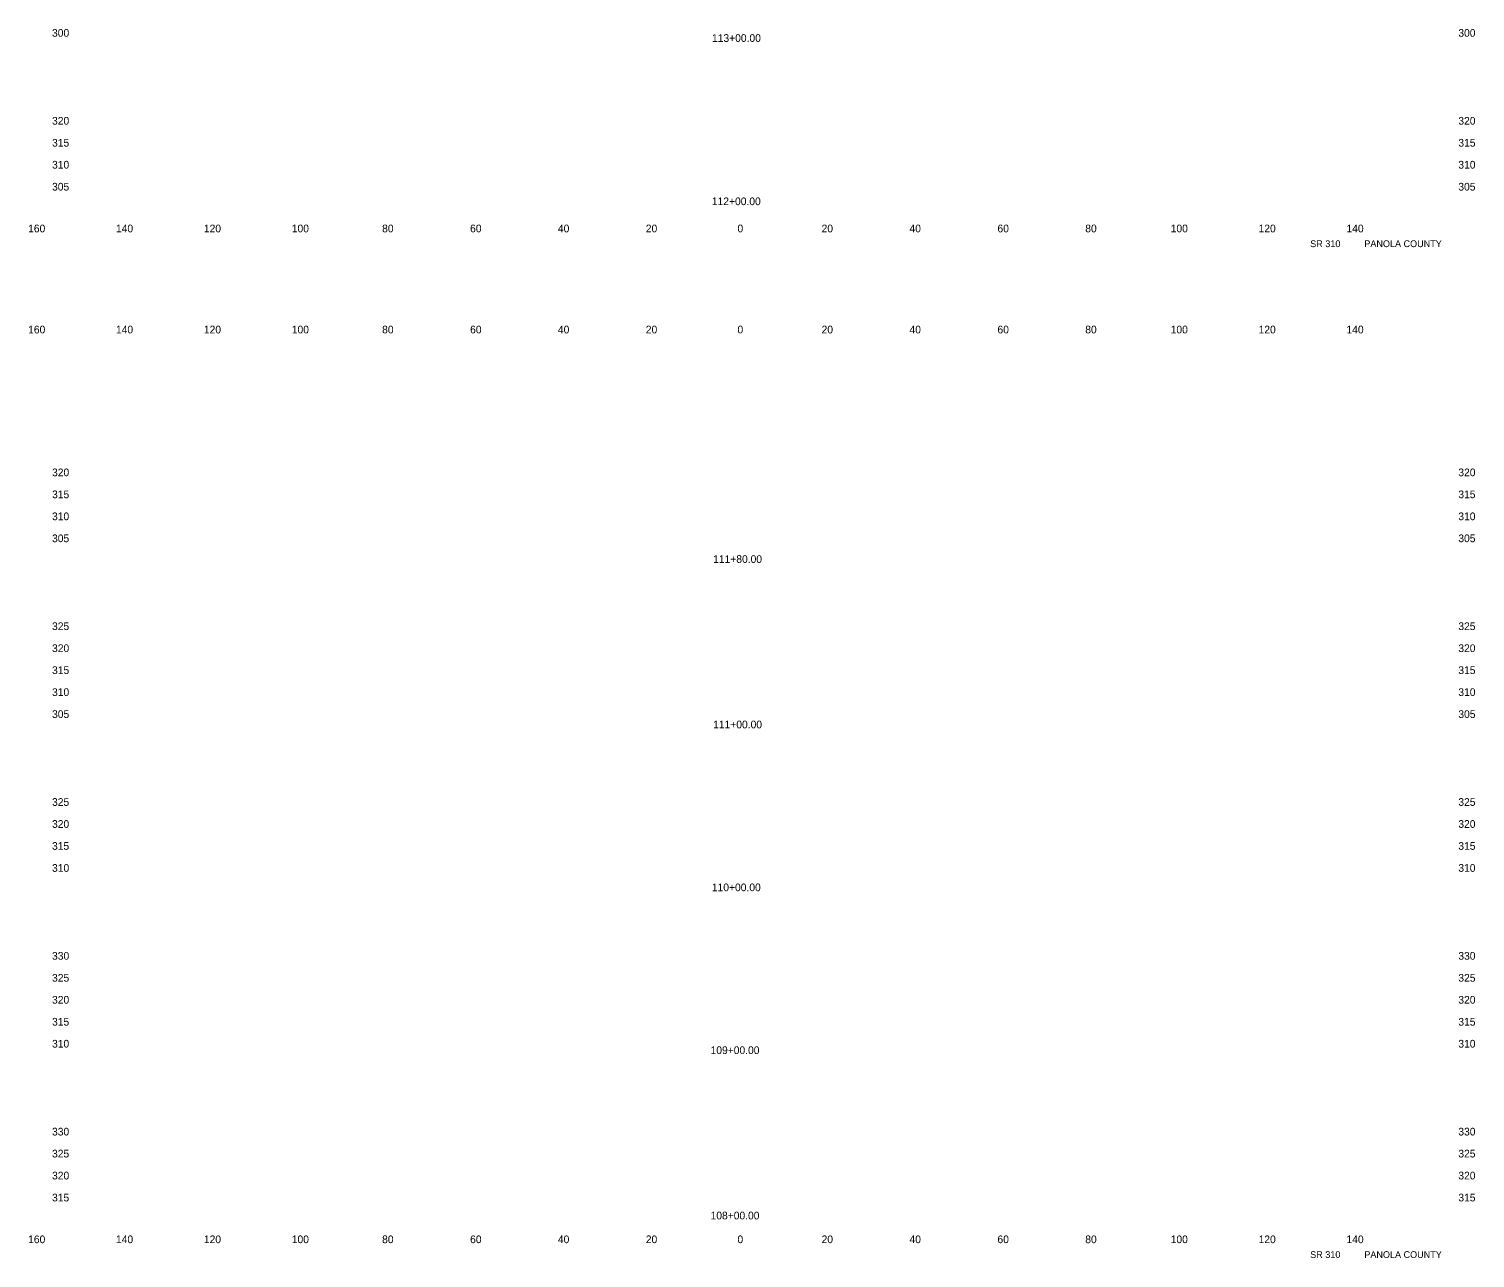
# Model space of a CAD drawing. Extents: x 21481 to 21810, y 6485 to 11067.
# Drawn here: x 21480.9 to 21809.9, y 7634.8 to 7914.5 of the extents above; entities that cross this region are included whole.
import ezdxf

# ---------------------------------------------------------------- set-up
doc = ezdxf.new("R2010")
doc.units = 0
for name, color, linetype in [('62', 7, 'Continuous'), ('XS_CELL', 7, 'Continuous'), ('XS_P_TX_DCH', 7, 'Continuous'), ('XS_P_TX_FS_BS', 7, 'Continuous')]:
    doc.layers.add(name, color=color, linetype=linetype)

msp = doc.modelspace()

# ---------------------------------------------------------------- texts
at = {"layer": '62'}
for s, p in [('  160  ', (21479.4, 7868.21)), ('  140  ', (21499.39, 7868.21)), ('  120  ', (21519.39, 7868.21)), ('  100  ', (21539.39, 7868.21)), ('  80  ', (21559.95, 7868.21)), ('  60  ', (21579.97, 7868.21)), ('  40  ', (21599.95, 7868.21)), ('  20  ', (21619.95, 7868.21)), ('  0  ', (21640.81, 7868.21)), ('  0  ', (21640.81, 7868.21)), ('  20  ', (21659.95, 7868.21)), ('  40  ', (21679.95, 7868.21)), ('  60  ', (21699.97, 7868.21)), ('  80  ', (21719.95, 7868.21)), ('  100  ', (21739.39, 7868.21)), ('  120  ', (21759.39, 7868.21)), ('  140  ', (21779.39, 7868.21)), ('  160  ', (21479.4, 7845.21)), ('  140  ', (21499.39, 7845.21)), ('  120  ', (21519.39, 7845.21)), ('  100  ', (21539.39, 7845.21)), ('  80  ', (21559.95, 7845.21)), ('  60  ', (21579.97, 7845.21)), ('  40  ', (21599.95, 7845.21)), ('  20  ', (21619.95, 7845.21)), ('  0  ', (21640.81, 7845.21)), ('  0  ', (21640.81, 7845.21)), ('  20  ', (21659.95, 7845.21)), ('  40  ', (21679.95, 7845.21)), ('  60  ', (21699.97, 7845.21)), ('  80  ', (21719.95, 7845.21)), ('  100  ', (21739.39, 7845.21)), ('  120  ', (21759.39, 7845.21)), ('  140  ', (21779.39, 7845.21)), ('  160  ', (21479.4, 7638.21)), ('  140  ', (21499.39, 7638.21)), ('  120  ', (21519.39, 7638.21)), ('  100  ', (21539.39, 7638.21)), ('  80  ', (21559.95, 7638.21)), ('  60  ', (21579.97, 7638.21)), ('  40  ', (21599.95, 7638.21)), ('  20  ', (21619.95, 7638.21)), ('  0  ', (21640.81, 7638.21)), ('  0  ', (21640.81, 7638.21)), ('  20  ', (21659.95, 7638.21)), ('  40  ', (21679.95, 7638.21)), ('  60  ', (21699.97, 7638.21)), ('  80  ', (21719.95, 7638.21)), ('  100  ', (21739.39, 7638.21)), ('  120  ', (21759.39, 7638.21)), ('  140  ', (21779.39, 7638.21))]:
    msp.add_text(s, height=1.75, dxfattribs=at).set_placement(p)
at = {"layer": 'XS_CELL'}
for s, p in [('  300  ', (21484.84, 7912.71)), ('  300  ', (21804.84, 7912.71)), ('  320  ', (21484.84, 7892.71)), ('  320  ', (21804.84, 7892.71)), ('  315  ', (21484.84, 7887.71)), ('  315  ', (21804.84, 7887.71)), ('  310  ', (21484.84, 7882.71)), ('  310  ', (21804.84, 7882.71)), ('  305  ', (21484.84, 7877.71)), ('  305  ', (21804.84, 7877.71)), ('  320  ', (21484.84, 7812.71)), ('  320  ', (21804.84, 7812.71)), ('  315  ', (21484.84, 7807.71)), ('  315  ', (21804.84, 7807.71)), ('  310  ', (21484.84, 7802.71)), ('  310  ', (21804.84, 7802.71)), ('  305  ', (21484.84, 7797.71)), ('  305  ', (21804.84, 7797.71)), ('  325  ', (21484.84, 7777.71)), ('  325  ', (21804.84, 7777.71)), ('  320  ', (21484.84, 7772.71)), ('  320  ', (21804.84, 7772.71)), ('  315  ', (21484.84, 7767.71)), ('  315  ', (21804.84, 7767.71)), ('  310  ', (21484.84, 7762.71)), ('  310  ', (21804.84, 7762.71)), ('  305  ', (21484.84, 7757.71)), ('  305  ', (21804.84, 7757.71)), ('  325  ', (21484.84, 7737.71)), ('  325  ', (21804.84, 7737.71)), ('  320  ', (21484.84, 7732.71)), ('  320  ', (21804.84, 7732.71)), ('  315  ', (21484.84, 7727.71)), ('  315  ', (21804.84, 7727.71)), ('  310  ', (21484.84, 7722.71)), ('  310  ', (21804.84, 7722.71)), ('  330  ', (21484.84, 7702.71)), ('  330  ', (21804.84, 7702.71)), ('  325  ', (21484.84, 7697.71)), ('  325  ', (21804.84, 7697.71)), ('  320  ', (21484.84, 7692.71)), ('  320  ', (21804.84, 7692.71)), ('  315  ', (21484.84, 7687.71)), ('  315  ', (21804.84, 7687.71)), ('  310  ', (21484.84, 7682.71)), ('  310  ', (21804.84, 7682.71)), ('  330  ', (21484.84, 7662.71)), ('  330  ', (21804.84, 7662.71)), ('  325  ', (21484.84, 7657.71)), ('  325  ', (21804.84, 7657.71)), ('  320  ', (21484.84, 7652.71)), ('  320  ', (21804.84, 7652.71)), ('  315  ', (21484.84, 7647.71)), ('  315  ', (21804.84, 7647.71))]:
    msp.add_text(s, height=1.75, dxfattribs=at).set_placement(p)
at = {"layer": 'XS_P_TX_DCH'}
for s, p in [('  113+00.00  ', (21635.01, 7911.54)), ('  112+00.00  ', (21634.98, 7874.39)), ('  111+80.00  ', (21635.27, 7792.99)), ('  111+00.00  ', (21635.27, 7755.35)), ('  110+00.00  ', (21634.98, 7718.29)), ('  109+00.00  ', (21634.69, 7681.24)), ('  108+00.00  ', (21634.69, 7643.62))]:
    msp.add_text(s, height=1.75, dxfattribs=at).set_placement(p)
at = {"layer": 'XS_P_TX_FS_BS'}
for s, p in [('SR 310', (21772.43, 7864.84)), ('SR 310', (21772.43, 7864.84)), ('SR 310', (21772.43, 7864.84)), ('PANOLA COUNTY', (21784.75, 7864.84)), ('PANOLA COUNTY', (21784.75, 7864.84)), ('PANOLA COUNTY', (21784.75, 7864.84)), ('SR 310', (21772.43, 7634.84)), ('SR 310', (21772.43, 7634.84)), ('SR 310', (21772.43, 7634.84)), ('PANOLA COUNTY', (21784.75, 7634.84)), ('PANOLA COUNTY', (21784.75, 7634.84)), ('PANOLA COUNTY', (21784.75, 7634.84))]:
    msp.add_text(s, height=1.54, dxfattribs=at).set_placement(p)

doc.saveas('drawing.dxf')
